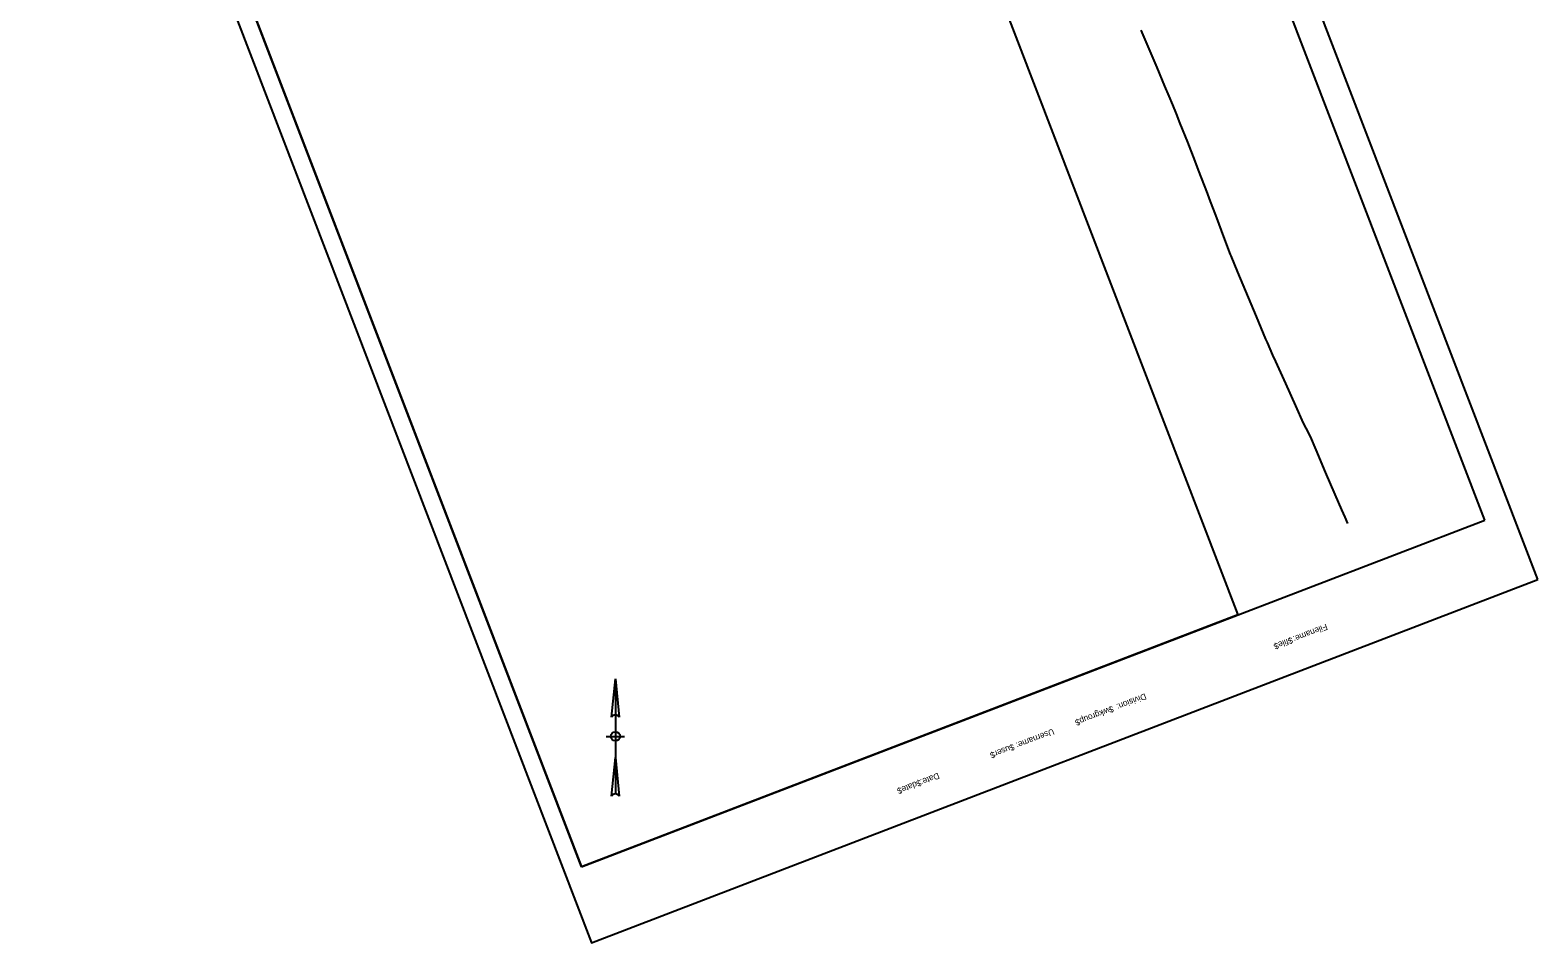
# Model space of a CAD drawing. Extents: x 1036948 to 1037766, y 782315 to 783306.
# Drawn here: x 1036948 to 1037766, y 782315 to 782811 of the extents above; entities that cross this region are included whole.
import ezdxf

# ---------------------------------------------------------------- set-up
doc = ezdxf.new("R2010")
doc.units = 0
for name, color, linetype in [('CLIPS', 7, 'Continuous'), ('D_Roadway_Centerline', 7, 'Continuous'), ('Default', 7, 'Continuous'), ('PLOT BOUNDARY', 7, 'Continuous')]:
    doc.layers.add(name, color=color, linetype=linetype)

msp = doc.modelspace()

# ---------------------------------------------------------------- linework, layer by layer
at = {"layer": 'CLIPS'}
msp.add_lwpolyline([(1037247.4, 782356.54), (1036978.62, 783056.73), (1037334.82, 783193.46), (1037603.59, 782493.27)], close=True, dxfattribs=at)
at = {"layer": 'D_Roadway_Centerline'}
msp.add_lwpolyline([(1037663.29, 782542.83), (1037661.68, 782546.38), (1037659.88, 782550.35), (1037656.37, 782558.52), (1037651.18, 782570.66), (1037646.01, 782582.8), (1037642.92, 782590.05), (1037640.57, 782594.69), (1037639.22, 782597.36), (1037634.97, 782606.76), (1037629.52, 782618.8), (1037624.08, 782630.83), (1037622.53, 782634.25), (1037619.56, 782641.07), (1037618.76, 782642.98), (1037613.66, 782655.15), (1037603.58, 782679.22), (1037599.88, 782688.08), (1037599.54, 782688.89), (1037595.95, 782698.42), (1037592.07, 782708.71), (1037588.19, 782719), (1037586.99, 782722.2), (1037582.26, 782734.61), (1037580.34, 782739.5), (1037576.33, 782749.73), (1037572.31, 782759.96), (1037570.27, 782765.16), (1037570.18, 782765.26), (1037568.17, 782770.1), (1037566.26, 782774.7), (1037566.25, 782774.74), (1037563.94, 782780.24), (1037559.67, 782790.37), (1037555.39, 782800.51), (1037554.33, 782803.04), (1037551.14, 782810.65)], dxfattribs=at)
at = {"layer": 'Default'}
for p, q in [((1037737.53, 782544.69), (1037450.84, 783291.55)), ((1036960.71, 783103.41), (1037247.4, 782356.54)), ((1037247.4, 782356.54), (1037737.53, 782544.69)), ((1037263.73, 782437.76), (1037265.81, 782458.59)), ((1037265.81, 782458.59), (1037265.81, 782396.09)), ((1037265.81, 782458.59), (1037267.9, 782437.76)), ((1037260.81, 782427.34), (1037270.81, 782427.34)), ((1037263.73, 782394.98), (1037265.81, 782415.81)), ((1037265.81, 782415.81), (1037267.9, 782394.98))]:
    msp.add_line(p, q, dxfattribs=at)
msp.add_circle((1037265.81, 782427.34), 2.5, dxfattribs=at)
for centre in [(1037265.81, 782436.38), (1037265.81, 782393.59)]:
    msp.add_arc(centre, 2.5, 33.55731, 146.44269, dxfattribs=at)
at = {"layer": 'PLOT BOUNDARY'}
msp.add_lwpolyline([(1037766.31, 782512.39), (1037461.7, 783305.93), (1036948.23, 783108.83), (1037252.84, 782315.29)], close=True, dxfattribs=at)

# ---------------------------------------------------------------- texts
at = {"layer": 'Default'}
for s, p in [('Filename:', (1037651.44, 782488.53)), ('$file$', (1037632.65, 782481.31)), ('Division:', (1037553.1, 782450.78)), ('$wkgroup$', (1037535.35, 782443.97)), ('Username:', (1037503.15, 782431.6)), ('$user$', (1037481.56, 782423.32)), ('Date:', (1037440.84, 782407.69)), ('$date$', (1037431.09, 782403.94))]:
    msp.add_text(s, height=3.348, rotation=201, dxfattribs=at).set_placement(p)

doc.saveas('drawing.dxf')
